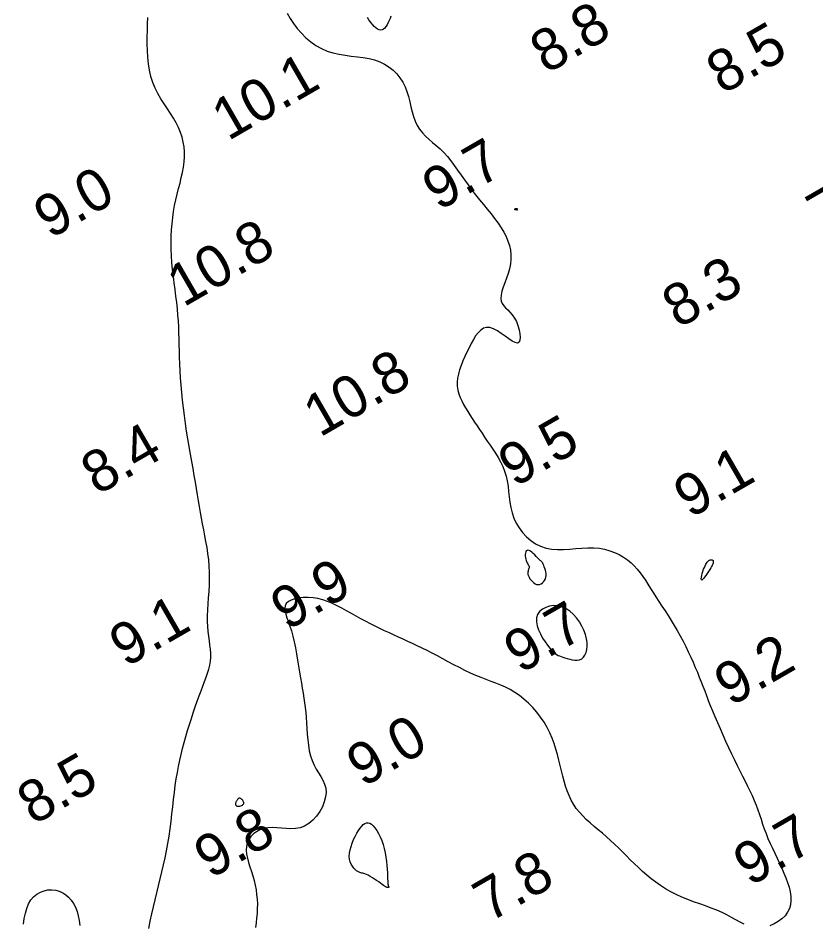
# Model space of a CAD drawing. Extents: x 3024098 to 3056816, y 418252 to 509144.
# Drawn here: x 3036807.6 to 3036902.9, y 419722.7 to 419830.9 of the extents above; entities that cross this region are included whole.
import ezdxf

# ---------------------------------------------------------------- set-up
doc = ezdxf.new("R2010")
doc.units = 0
doc.layers.add('V-CHAN-CONT-EL10', color=7, linetype='Continuous')
doc.layers.add('V-TOPO-SOUN-0911', color=7, linetype='Continuous')

msp = doc.modelspace()

# ---------------------------------------------------------------- linework, layer by layer
at = {"layer": 'V-CHAN-CONT-EL10'}
for points in [[(3036823.2, 419722.15), (3036823.37, 419723.02), (3036823.55, 419723.88), (3036823.75, 419724.73), (3036823.95, 419725.58), (3036824.16, 419726.42), (3036824.37, 419727.25), (3036824.57, 419728.08), (3036824.77, 419728.91), (3036824.97, 419729.74), (3036825.15, 419730.58), (3036825.32, 419731.43), (3036825.48, 419732.29), (3036825.61, 419733.16), (3036825.74, 419734.04), (3036825.85, 419734.93), (3036825.95, 419735.82), (3036826.05, 419736.69), (3036826.15, 419737.55), (3036826.25, 419738.4), (3036826.36, 419739.22), (3036826.48, 419740), (3036826.61, 419740.77), (3036826.75, 419741.51), (3036826.9, 419742.23), (3036827.06, 419742.94), (3036827.23, 419743.65), (3036827.42, 419744.35), (3036827.62, 419745.06), (3036827.83, 419745.78), (3036828.05, 419746.5), (3036828.28, 419747.21), (3036828.51, 419747.92), (3036828.75, 419748.61), (3036828.98, 419749.28), (3036829.21, 419749.92), (3036829.44, 419750.53), (3036829.66, 419751.1), (3036829.86, 419751.65), (3036830.05, 419752.16), (3036830.22, 419752.66), (3036830.36, 419753.13), (3036830.47, 419753.6), (3036830.55, 419754.07), (3036830.59, 419754.53), (3036830.59, 419755), (3036830.55, 419755.49), (3036830.5, 419755.99), (3036830.43, 419756.5), (3036830.35, 419757.04), (3036830.29, 419757.61), (3036830.23, 419758.2), (3036830.21, 419758.83), (3036830.21, 419759.5), (3036830.24, 419760.19), (3036830.28, 419760.91), (3036830.33, 419761.65), (3036830.39, 419762.41), (3036830.43, 419763.17), (3036830.45, 419763.93), (3036830.45, 419764.69), (3036830.42, 419765.44), (3036830.35, 419766.18), (3036830.26, 419766.92), (3036830.15, 419767.64), (3036830.02, 419768.35), (3036829.89, 419769.06), (3036829.75, 419769.77), (3036829.62, 419770.46), (3036829.49, 419771.15), (3036829.37, 419771.84), (3036829.26, 419772.54), (3036829.14, 419773.24), (3036829.02, 419773.96), (3036828.9, 419774.69), (3036828.77, 419775.46), (3036828.63, 419776.25), (3036828.49, 419777.07), (3036828.33, 419777.93), (3036828.18, 419778.81), (3036828.02, 419779.71), (3036827.86, 419780.62), (3036827.71, 419781.55), (3036827.57, 419782.48), (3036827.44, 419783.41), (3036827.33, 419784.33), (3036827.23, 419785.25), (3036827.14, 419786.16), (3036827.07, 419787.05), (3036827, 419787.92), (3036826.95, 419788.77), (3036826.91, 419789.59), (3036826.88, 419790.39), (3036826.85, 419791.15), (3036826.83, 419791.88), (3036826.81, 419792.6), (3036826.79, 419793.3), (3036826.77, 419794.01), (3036826.73, 419794.71), (3036826.68, 419795.42), (3036826.62, 419796.15), (3036826.54, 419796.9), (3036826.44, 419797.67), (3036826.34, 419798.46), (3036826.24, 419799.26), (3036826.14, 419800.06), (3036826.04, 419800.87), (3036825.96, 419801.68), (3036825.9, 419802.48), (3036825.87, 419803.27), (3036825.86, 419804.05), (3036825.87, 419804.82), (3036825.91, 419805.58), (3036825.97, 419806.33), (3036826.05, 419807.06), (3036826.16, 419807.78), (3036826.28, 419808.49), (3036826.43, 419809.18), (3036826.59, 419809.86), (3036826.76, 419810.53), (3036826.93, 419811.18), (3036827.08, 419811.83), (3036827.22, 419812.46), (3036827.33, 419813.08), (3036827.41, 419813.7), (3036827.45, 419814.3), (3036827.45, 419814.9), (3036827.4, 419815.49), (3036827.31, 419816.08), (3036827.17, 419816.66), (3036826.99, 419817.23), (3036826.76, 419817.8), (3036826.48, 419818.37), (3036826.16, 419818.93), (3036825.8, 419819.49), (3036825.42, 419820.06), (3036825.03, 419820.65), (3036824.65, 419821.24), (3036824.29, 419821.86), (3036823.96, 419822.51), (3036823.68, 419823.19), (3036823.45, 419823.9), (3036823.28, 419824.65), (3036823.16, 419825.42), (3036823.08, 419826.21), (3036823.03, 419827), (3036823.01, 419827.81), (3036823.01, 419828.61), (3036823.03, 419829.41), (3036823.05, 419830.19), (3036823.09, 419830.97)], [(3036839.73, 419831.47), (3036840.08, 419830.85), (3036840.48, 419830.23), (3036840.93, 419829.64), (3036841.42, 419829.07), (3036841.96, 419828.54), (3036842.54, 419828.05), (3036843.16, 419827.62), (3036843.81, 419827.25), (3036844.49, 419826.95), (3036845.19, 419826.72), (3036845.92, 419826.56), (3036846.65, 419826.44), (3036847.38, 419826.35), (3036848.11, 419826.26), (3036848.82, 419826.17), (3036849.51, 419826.05), (3036850.17, 419825.88), (3036850.78, 419825.66), (3036851.36, 419825.38), (3036851.89, 419825.04), (3036852.38, 419824.65), (3036852.81, 419824.22), (3036853.2, 419823.74), (3036853.53, 419823.23), (3036853.81, 419822.68), (3036854.03, 419822.11), (3036854.22, 419821.51), (3036854.37, 419820.9), (3036854.51, 419820.3), (3036854.66, 419819.7), (3036854.82, 419819.12), (3036855.01, 419818.58), (3036855.24, 419818.07), (3036855.53, 419817.61), (3036855.87, 419817.19), (3036856.25, 419816.79), (3036856.66, 419816.41), (3036857.1, 419816.04), (3036857.54, 419815.65), (3036857.99, 419815.25), (3036858.43, 419814.82), (3036858.86, 419814.34), (3036859.28, 419813.83), (3036859.69, 419813.29), (3036860.09, 419812.72), (3036860.5, 419812.14), (3036860.92, 419811.55), (3036861.34, 419810.95), (3036861.78, 419810.35), (3036862.23, 419809.77), (3036862.7, 419809.18), (3036863.16, 419808.61), (3036863.63, 419808.05), (3036864.08, 419807.49), (3036864.5, 419806.93), (3036864.91, 419806.39), (3036865.27, 419805.85), (3036865.6, 419805.31), (3036865.87, 419804.78), (3036866.1, 419804.24), (3036866.27, 419803.71), (3036866.4, 419803.17), (3036866.46, 419802.63), (3036866.46, 419802.08), (3036866.4, 419801.52), (3036866.28, 419800.95), (3036866.12, 419800.38), (3036865.92, 419799.81), (3036865.72, 419799.26), (3036865.53, 419798.74), (3036865.38, 419798.25), (3036865.27, 419797.8), (3036865.23, 419797.41), (3036865.28, 419797.07), (3036865.4, 419796.78), (3036865.59, 419796.52), (3036865.81, 419796.27), (3036866.07, 419796.02), (3036866.34, 419795.74), (3036866.61, 419795.43), (3036866.87, 419795.06), (3036867.1, 419794.63), (3036867.29, 419794.15), (3036867.43, 419793.66), (3036867.53, 419793.19), (3036867.56, 419792.77), (3036867.53, 419792.42), (3036867.42, 419792.17), (3036867.23, 419792.07), (3036866.96, 419792.12), (3036866.61, 419792.3), (3036866.21, 419792.57), (3036865.77, 419792.89), (3036865.3, 419793.23), (3036864.83, 419793.54), (3036864.37, 419793.78), (3036863.93, 419793.93), (3036863.53, 419793.94), (3036863.17, 419793.83), (3036862.84, 419793.61), (3036862.53, 419793.31), (3036862.24, 419792.93), (3036861.97, 419792.49), (3036861.71, 419792), (3036861.45, 419791.5), (3036861.2, 419790.98), (3036860.95, 419790.45), (3036860.71, 419789.93), (3036860.5, 419789.4), (3036860.32, 419788.88), (3036860.18, 419788.37), (3036860.08, 419787.87), (3036860.03, 419787.38), (3036860.05, 419786.91), (3036860.11, 419786.46), (3036860.23, 419786.01), (3036860.39, 419785.58), (3036860.58, 419785.16), (3036860.8, 419784.74), (3036861.04, 419784.32), (3036861.3, 419783.9), (3036861.56, 419783.48), (3036861.83, 419783.05), (3036862.11, 419782.62), (3036862.4, 419782.18), (3036862.69, 419781.74), (3036863, 419781.29), (3036863.31, 419780.83), (3036863.63, 419780.36), (3036863.96, 419779.89), (3036864.29, 419779.4), (3036864.62, 419778.91), (3036864.93, 419778.4), (3036865.22, 419777.87), (3036865.48, 419777.33), (3036865.7, 419776.77), (3036865.88, 419776.19), (3036866.01, 419775.6), (3036866.11, 419774.98), (3036866.18, 419774.35), (3036866.25, 419773.71), (3036866.33, 419773.07), (3036866.44, 419772.43), (3036866.59, 419771.8), (3036866.8, 419771.17), (3036867.08, 419770.56), (3036867.43, 419769.98), (3036867.84, 419769.43), (3036868.31, 419768.93), (3036868.83, 419768.48), (3036869.4, 419768.1), (3036870, 419767.79), (3036870.65, 419767.58), (3036871.33, 419767.45), (3036872.03, 419767.4), (3036872.75, 419767.41), (3036873.48, 419767.45), (3036874.21, 419767.52), (3036874.94, 419767.58), (3036875.65, 419767.62), (3036876.35, 419767.61), (3036877.02, 419767.56), (3036877.65, 419767.44), (3036878.27, 419767.27), (3036878.84, 419767.06), (3036879.39, 419766.8), (3036879.9, 419766.51), (3036880.37, 419766.19), (3036880.8, 419765.83), (3036881.19, 419765.45), (3036881.55, 419765.05), (3036881.89, 419764.63), (3036882.2, 419764.19), (3036882.51, 419763.73), (3036882.81, 419763.26), (3036883.12, 419762.77), (3036883.44, 419762.26), (3036883.77, 419761.74), (3036884.12, 419761.21), (3036884.48, 419760.66), (3036884.86, 419760.1), (3036885.23, 419759.53), (3036885.6, 419758.94), (3036885.97, 419758.34), (3036886.33, 419757.73), (3036886.68, 419757.11), (3036887.02, 419756.47), (3036887.34, 419755.83), (3036887.64, 419755.2), (3036887.94, 419754.56), (3036888.21, 419753.94), (3036888.48, 419753.33), (3036888.72, 419752.74), (3036888.95, 419752.17), (3036889.17, 419751.62), (3036889.38, 419751.07), (3036889.6, 419750.53), (3036889.81, 419749.97), (3036890.03, 419749.39), (3036890.27, 419748.79), (3036890.53, 419748.15), (3036890.81, 419747.47), (3036891.11, 419746.75), (3036891.43, 419746.02), (3036891.76, 419745.26), (3036892.1, 419744.51), (3036892.45, 419743.75), (3036892.8, 419743.02), (3036893.14, 419742.3), (3036893.48, 419741.62), (3036893.81, 419740.97), (3036894.13, 419740.34), (3036894.44, 419739.73), (3036894.73, 419739.15), (3036895.01, 419738.57), (3036895.27, 419738.01), (3036895.51, 419737.44), (3036895.73, 419736.88), (3036895.94, 419736.32), (3036896.14, 419735.76), (3036896.33, 419735.19), (3036896.52, 419734.62), (3036896.72, 419734.05), (3036896.93, 419733.48), (3036897.16, 419732.9), (3036897.42, 419732.31), (3036897.69, 419731.72), (3036897.97, 419731.13), (3036898.25, 419730.54), (3036898.54, 419729.94), (3036898.81, 419729.35), (3036899.07, 419728.77), (3036899.3, 419728.19), (3036899.51, 419727.62), (3036899.68, 419727.06), (3036899.81, 419726.51), (3036899.88, 419725.98), (3036899.89, 419725.47), (3036899.84, 419724.98), (3036899.71, 419724.52), (3036899.5, 419724.08), (3036899.2, 419723.67), (3036898.82, 419723.3), (3036898.39, 419722.98), (3036897.9, 419722.7), (3036897.38, 419722.48)], [(3036852.12, 419831.1), (3036852.02, 419830.85), (3036851.9, 419830.59), (3036851.78, 419830.34), (3036851.66, 419830.1), (3036851.52, 419829.89), (3036851.38, 419829.7), (3036851.23, 419829.56), (3036851.07, 419829.47), (3036850.89, 419829.44), (3036850.7, 419829.48), (3036850.51, 419829.58), (3036850.31, 419829.72), (3036850.12, 419829.9), (3036849.94, 419830.1), (3036849.76, 419830.3), (3036849.61, 419830.5), (3036849.48, 419830.68), (3036849.38, 419830.84), (3036849.31, 419830.97)], [(3036894.3, 419722.65), (3036893.82, 419722.89), (3036893.32, 419723.17), (3036892.81, 419723.46), (3036892.26, 419723.76), (3036891.68, 419724.06), (3036891.06, 419724.33), (3036890.39, 419724.59), (3036889.7, 419724.84), (3036889, 419725.09), (3036888.28, 419725.34), (3036887.57, 419725.6), (3036886.87, 419725.88), (3036886.19, 419726.19), (3036885.54, 419726.52), (3036884.93, 419726.88), (3036884.33, 419727.26), (3036883.76, 419727.66), (3036883.22, 419728.08), (3036882.69, 419728.52), (3036882.18, 419728.97), (3036881.68, 419729.42), (3036881.19, 419729.89), (3036880.71, 419730.35), (3036880.24, 419730.82), (3036879.77, 419731.29), (3036879.3, 419731.76), (3036878.83, 419732.21), (3036878.35, 419732.66), (3036877.87, 419733.1), (3036877.38, 419733.52), (3036876.89, 419733.93), (3036876.4, 419734.34), (3036875.92, 419734.75), (3036875.46, 419735.16), (3036875.03, 419735.59), (3036874.63, 419736.03), (3036874.26, 419736.49), (3036873.94, 419736.98), (3036873.66, 419737.49), (3036873.41, 419738.02), (3036873.19, 419738.58), (3036872.99, 419739.15), (3036872.82, 419739.74), (3036872.65, 419740.35), (3036872.5, 419740.98), (3036872.34, 419741.61), (3036872.19, 419742.26), (3036872.02, 419742.92), (3036871.83, 419743.57), (3036871.62, 419744.23), (3036871.38, 419744.89), (3036871.1, 419745.53), (3036870.78, 419746.17), (3036870.41, 419746.8), (3036869.99, 419747.4), (3036869.54, 419747.98), (3036869.05, 419748.54), (3036868.54, 419749.05), (3036868.01, 419749.53), (3036867.46, 419749.97), (3036866.91, 419750.35), (3036866.35, 419750.68), (3036865.8, 419750.96), (3036865.23, 419751.21), (3036864.66, 419751.44), (3036864.08, 419751.66), (3036863.49, 419751.88), (3036862.88, 419752.11), (3036862.26, 419752.36), (3036861.62, 419752.65), (3036860.96, 419752.97), (3036860.3, 419753.3), (3036859.64, 419753.65), (3036858.97, 419754.01), (3036858.31, 419754.36), (3036857.67, 419754.71), (3036857.04, 419755.04), (3036856.43, 419755.35), (3036855.84, 419755.64), (3036855.26, 419755.92), (3036854.7, 419756.18), (3036854.14, 419756.44), (3036853.59, 419756.69), (3036853.04, 419756.94), (3036852.49, 419757.19), (3036851.93, 419757.45), (3036851.36, 419757.71), (3036850.8, 419757.98), (3036850.23, 419758.26), (3036849.66, 419758.55), (3036849.09, 419758.84), (3036848.52, 419759.14), (3036847.95, 419759.45), (3036847.39, 419759.77), (3036846.83, 419760.09), (3036846.27, 419760.4), (3036845.7, 419760.69), (3036845.14, 419760.96), (3036844.56, 419761.2), (3036843.99, 419761.4), (3036843.4, 419761.55), (3036842.81, 419761.65), (3036842.22, 419761.69), (3036841.65, 419761.68), (3036841.12, 419761.62), (3036840.63, 419761.52), (3036840.21, 419761.37), (3036839.87, 419761.19), (3036839.62, 419760.96), (3036839.48, 419760.7), (3036839.44, 419760.41), (3036839.47, 419760.07), (3036839.56, 419759.69), (3036839.7, 419759.26), (3036839.87, 419758.79), (3036840.06, 419758.26), (3036840.25, 419757.68), (3036840.42, 419757.05), (3036840.57, 419756.37), (3036840.72, 419755.66), (3036840.85, 419754.93), (3036840.97, 419754.2), (3036841.09, 419753.47), (3036841.2, 419752.76), (3036841.31, 419752.08), (3036841.42, 419751.43), (3036841.52, 419750.83), (3036841.62, 419750.24), (3036841.71, 419749.67), (3036841.8, 419749.11), (3036841.87, 419748.54), (3036841.94, 419747.96), (3036842, 419747.35), (3036842.04, 419746.71), (3036842.09, 419746.04), (3036842.13, 419745.37), (3036842.19, 419744.69), (3036842.27, 419744.03), (3036842.37, 419743.38), (3036842.51, 419742.76), (3036842.7, 419742.19), (3036842.93, 419741.67), (3036843.2, 419741.18), (3036843.48, 419740.72), (3036843.75, 419740.28), (3036844, 419739.84), (3036844.19, 419739.39), (3036844.33, 419738.91), (3036844.37, 419738.4), (3036844.32, 419737.85), (3036844.16, 419737.27), (3036843.93, 419736.68), (3036843.61, 419736.1), (3036843.24, 419735.56), (3036842.8, 419735.08), (3036842.33, 419734.67), (3036841.81, 419734.37), (3036841.28, 419734.18), (3036840.73, 419734.08), (3036840.16, 419734.05), (3036839.59, 419734.08), (3036839.03, 419734.12), (3036838.47, 419734.17), (3036837.93, 419734.19), (3036837.41, 419734.17), (3036836.93, 419734.08), (3036836.47, 419733.92), (3036836.06, 419733.7), (3036835.7, 419733.43), (3036835.39, 419733.12), (3036835.14, 419732.76), (3036834.96, 419732.36), (3036834.86, 419731.94), (3036834.84, 419731.49), (3036834.88, 419731.02), (3036834.98, 419730.53), (3036835.11, 419730.02), (3036835.27, 419729.5), (3036835.45, 419728.97), (3036835.62, 419728.43), (3036835.78, 419727.88), (3036835.91, 419727.32), (3036836.01, 419726.76), (3036836.08, 419726.2), (3036836.13, 419725.63), (3036836.16, 419725.07), (3036836.15, 419724.5), (3036836.13, 419723.94), (3036836.08, 419723.38), (3036836.02, 419722.82), (3036835.93, 419722.27)], [(3036808.23, 419722.66), (3036808.32, 419723.33), (3036808.45, 419723.97), (3036808.62, 419724.55), (3036808.84, 419725.09), (3036809.11, 419725.55), (3036809.44, 419725.94), (3036809.82, 419726.26), (3036810.24, 419726.49), (3036810.69, 419726.66), (3036811.15, 419726.75), (3036811.61, 419726.77), (3036812.07, 419726.72), (3036812.5, 419726.6), (3036812.91, 419726.42), (3036813.28, 419726.18), (3036813.62, 419725.89), (3036813.93, 419725.53), (3036814.19, 419725.13), (3036814.42, 419724.68), (3036814.62, 419724.19), (3036814.76, 419723.66), (3036814.87, 419723.1), (3036814.95, 419722.51)]]:
    msp.add_lwpolyline(points, dxfattribs=at)
for points in [[(3036866.9, 419808.04), (3036866.9, 419808.05), (3036866.91, 419808.07), (3036866.92, 419808.09), (3036866.94, 419808.1), (3036866.96, 419808.12), (3036866.98, 419808.13), (3036867, 419808.14), (3036867.02, 419808.15), (3036867.05, 419808.16), (3036867.07, 419808.16), (3036867.1, 419808.16), (3036867.12, 419808.16), (3036867.14, 419808.15), (3036867.16, 419808.14), (3036867.18, 419808.13), (3036867.19, 419808.11), (3036867.21, 419808.09), (3036867.21, 419808.07), (3036867.22, 419808.04), (3036867.22, 419808.02), (3036867.22, 419808.01), (3036867.21, 419807.99), (3036867.21, 419807.98), (3036867.19, 419807.97), (3036867.18, 419807.96), (3036867.16, 419807.96), (3036867.14, 419807.96), (3036867.11, 419807.97), (3036867.09, 419807.97), (3036867.06, 419807.98), (3036867.04, 419807.98), (3036867.01, 419807.99), (3036866.99, 419807.99), (3036866.96, 419807.99), (3036866.94, 419808), (3036866.93, 419808), (3036866.91, 419808.01), (3036866.9, 419808.02), (3036866.9, 419808.03)], [(3036870.66, 419764.3), (3036870.66, 419764.52), (3036870.63, 419764.74), (3036870.58, 419764.96), (3036870.52, 419765.16), (3036870.44, 419765.35), (3036870.37, 419765.52), (3036870.31, 419765.66), (3036870.25, 419765.77), (3036870.2, 419765.86), (3036870.15, 419765.92), (3036870.09, 419765.98), (3036870.03, 419766.04), (3036869.96, 419766.11), (3036869.87, 419766.19), (3036869.76, 419766.3), (3036869.62, 419766.43), (3036869.47, 419766.59), (3036869.3, 419766.76), (3036869.12, 419766.93), (3036868.95, 419767.08), (3036868.78, 419767.2), (3036868.62, 419767.29), (3036868.49, 419767.33), (3036868.38, 419767.31), (3036868.29, 419767.24), (3036868.23, 419767.13), (3036868.19, 419766.98), (3036868.17, 419766.81), (3036868.17, 419766.63), (3036868.19, 419766.45), (3036868.22, 419766.27), (3036868.27, 419766.11), (3036868.33, 419765.96), (3036868.4, 419765.83), (3036868.47, 419765.71), (3036868.53, 419765.6), (3036868.58, 419765.49), (3036868.62, 419765.39), (3036868.64, 419765.3), (3036868.63, 419765.21), (3036868.61, 419765.13), (3036868.57, 419765.04), (3036868.53, 419764.94), (3036868.5, 419764.84), (3036868.47, 419764.72), (3036868.47, 419764.59), (3036868.49, 419764.44), (3036868.54, 419764.27), (3036868.62, 419764.09), (3036868.73, 419763.91), (3036868.86, 419763.73), (3036869.01, 419763.57), (3036869.17, 419763.42), (3036869.34, 419763.32), (3036869.52, 419763.25), (3036869.7, 419763.23), (3036869.88, 419763.25), (3036870.06, 419763.32), (3036870.22, 419763.42), (3036870.36, 419763.55), (3036870.48, 419763.71), (3036870.58, 419763.89), (3036870.64, 419764.09)], [(3036889.65, 419765.48), (3036889.73, 419765.64), (3036889.81, 419765.78), (3036889.89, 419765.89), (3036889.97, 419765.98), (3036890.04, 419766.04), (3036890.11, 419766.1), (3036890.18, 419766.13), (3036890.24, 419766.16), (3036890.3, 419766.17), (3036890.36, 419766.18), (3036890.41, 419766.18), (3036890.45, 419766.17), (3036890.49, 419766.16), (3036890.53, 419766.14), (3036890.56, 419766.12), (3036890.58, 419766.1), (3036890.6, 419766.08), (3036890.61, 419766.06), (3036890.62, 419766.03), (3036890.62, 419766.01), (3036890.63, 419765.99), (3036890.63, 419765.96), (3036890.62, 419765.94), (3036890.62, 419765.92), (3036890.62, 419765.9), (3036890.62, 419765.88), (3036890.62, 419765.86), (3036890.61, 419765.84), (3036890.61, 419765.82), (3036890.61, 419765.8), (3036890.61, 419765.79), (3036890.61, 419765.77), (3036890.61, 419765.75), (3036890.6, 419765.72), (3036890.58, 419765.68), (3036890.55, 419765.61), (3036890.5, 419765.52), (3036890.43, 419765.39), (3036890.33, 419765.23), (3036890.2, 419765.02), (3036890.06, 419764.79), (3036889.9, 419764.55), (3036889.74, 419764.31), (3036889.59, 419764.1), (3036889.45, 419763.93), (3036889.33, 419763.81), (3036889.25, 419763.76), (3036889.2, 419763.8), (3036889.19, 419763.92), (3036889.21, 419764.09), (3036889.25, 419764.3), (3036889.31, 419764.54), (3036889.39, 419764.8), (3036889.47, 419765.05), (3036889.56, 419765.28)], [(3036875.12, 419754.54), (3036875.3, 419754.79), (3036875.44, 419755.09), (3036875.53, 419755.45), (3036875.57, 419755.85), (3036875.56, 419756.29), (3036875.5, 419756.76), (3036875.37, 419757.25), (3036875.18, 419757.76), (3036874.94, 419758.27), (3036874.64, 419758.77), (3036874.29, 419759.24), (3036873.9, 419759.67), (3036873.48, 419760.05), (3036873.02, 419760.35), (3036872.54, 419760.57), (3036872.04, 419760.68), (3036871.54, 419760.71), (3036871.06, 419760.64), (3036870.61, 419760.5), (3036870.21, 419760.28), (3036869.88, 419759.99), (3036869.64, 419759.64), (3036869.51, 419759.24), (3036869.49, 419758.79), (3036869.57, 419758.31), (3036869.74, 419757.82), (3036869.97, 419757.32), (3036870.24, 419756.83), (3036870.54, 419756.38), (3036870.83, 419755.97), (3036871.1, 419755.62), (3036871.34, 419755.35), (3036871.55, 419755.14), (3036871.73, 419754.98), (3036871.91, 419754.86), (3036872.08, 419754.77), (3036872.25, 419754.7), (3036872.45, 419754.64), (3036872.66, 419754.57), (3036872.91, 419754.49), (3036873.19, 419754.4), (3036873.48, 419754.31), (3036873.78, 419754.25), (3036874.09, 419754.21), (3036874.38, 419754.21), (3036874.66, 419754.25), (3036874.91, 419754.36)], [(3036833.97, 419736.75), (3036834.07, 419736.77), (3036834.18, 419736.8), (3036834.27, 419736.84), (3036834.37, 419736.89), (3036834.44, 419736.95), (3036834.5, 419737.01), (3036834.54, 419737.09), (3036834.54, 419737.17), (3036834.52, 419737.26), (3036834.48, 419737.34), (3036834.43, 419737.42), (3036834.37, 419737.5), (3036834.29, 419737.57), (3036834.22, 419737.63), (3036834.15, 419737.67), (3036834.09, 419737.7), (3036834.03, 419737.71), (3036833.98, 419737.71), (3036833.94, 419737.7), (3036833.9, 419737.67), (3036833.85, 419737.63), (3036833.82, 419737.59), (3036833.78, 419737.54), (3036833.74, 419737.49), (3036833.7, 419737.43), (3036833.66, 419737.37), (3036833.63, 419737.31), (3036833.6, 419737.24), (3036833.58, 419737.18), (3036833.56, 419737.11), (3036833.56, 419737.05), (3036833.56, 419736.99), (3036833.57, 419736.93), (3036833.59, 419736.88), (3036833.63, 419736.84), (3036833.67, 419736.8), (3036833.73, 419736.77), (3036833.8, 419736.75), (3036833.88, 419736.74)], [(3036847.16, 419731.13), (3036847.23, 419731.52), (3036847.35, 419731.93), (3036847.49, 419732.35), (3036847.66, 419732.76), (3036847.85, 419733.15), (3036848.05, 419733.51), (3036848.25, 419733.84), (3036848.44, 419734.13), (3036848.63, 419734.37), (3036848.82, 419734.55), (3036849.01, 419734.68), (3036849.19, 419734.76), (3036849.39, 419734.77), (3036849.58, 419734.72), (3036849.79, 419734.6), (3036850, 419734.41), (3036850.21, 419734.16), (3036850.42, 419733.85), (3036850.63, 419733.49), (3036850.83, 419733.09), (3036851.02, 419732.65), (3036851.18, 419732.18), (3036851.32, 419731.68), (3036851.43, 419731.18), (3036851.52, 419730.67), (3036851.59, 419730.16), (3036851.64, 419729.67), (3036851.67, 419729.21), (3036851.69, 419728.78), (3036851.71, 419728.4), (3036851.72, 419728.07), (3036851.73, 419727.81), (3036851.74, 419727.62), (3036851.75, 419727.47), (3036851.77, 419727.36), (3036851.78, 419727.29), (3036851.79, 419727.24), (3036851.8, 419727.21), (3036851.82, 419727.19), (3036851.83, 419727.17), (3036851.84, 419727.15), (3036851.85, 419727.12), (3036851.86, 419727.1), (3036851.87, 419727.09), (3036851.87, 419727.07), (3036851.87, 419727.05), (3036851.86, 419727.04), (3036851.84, 419727.03), (3036851.82, 419727.03), (3036851.79, 419727.03), (3036851.76, 419727.03), (3036851.73, 419727.03), (3036851.7, 419727.03), (3036851.67, 419727.04), (3036851.64, 419727.04), (3036851.62, 419727.05), (3036851.59, 419727.06), (3036851.55, 419727.08), (3036851.5, 419727.1), (3036851.44, 419727.15), (3036851.35, 419727.21), (3036851.23, 419727.29), (3036851.07, 419727.4), (3036850.88, 419727.54), (3036850.66, 419727.7), (3036850.41, 419727.86), (3036850.15, 419728.04), (3036849.9, 419728.21), (3036849.64, 419728.36), (3036849.41, 419728.5), (3036849.2, 419728.61), (3036849.02, 419728.68), (3036848.88, 419728.73), (3036848.75, 419728.76), (3036848.64, 419728.77), (3036848.53, 419728.79), (3036848.42, 419728.82), (3036848.31, 419728.86), (3036848.17, 419728.94), (3036848.02, 419729.04), (3036847.85, 419729.18), (3036847.68, 419729.36), (3036847.52, 419729.57), (3036847.38, 419729.82), (3036847.26, 419730.1), (3036847.18, 419730.41), (3036847.14, 419730.75)]]:
    msp.add_lwpolyline(points, close=True, dxfattribs=at)

# ---------------------------------------------------------------- texts
at = {"layer": 'V-TOPO-SOUN-0911'}
for s, p in [('8.8', (3036870.68, 419824.16)), ('8.5', (3036891.74, 419821.7)), ('10.1 ', (3036832.67, 419816.16)), ('9.7', (3036857.82, 419807.79)), ('7.7', (3036903.75, 419804.97)), ('9.0', (3036811.41, 419804.44)), ('10.8 ', (3036827.34, 419796.3)), ('8.3', (3036886.46, 419793.75)), ('10.8 ', (3036843.62, 419780.75)), ('9.5', (3036866.9, 419774.78)), ('8.4', (3036817.04, 419773.83)), ('9.1', (3036887.86, 419771.06)), ('9.9', (3036839.71, 419757.66)), ('9.1', (3036820.44, 419753.27)), ('9.7', (3036867.57, 419752.51)), ('9.2', (3036892.7, 419748.6)), ('9.0', (3036848.78, 419738.95)), ('8.5', (3036809.42, 419734.43)), ('9.8', (3036830.56, 419728)), ('9.7', (3036894.99, 419727.11)), ('7.8', (3036863.89, 419722.81))]:
    msp.add_text(s, height=5, rotation=30, dxfattribs=at).set_placement(p)

doc.saveas('drawing.dxf')
